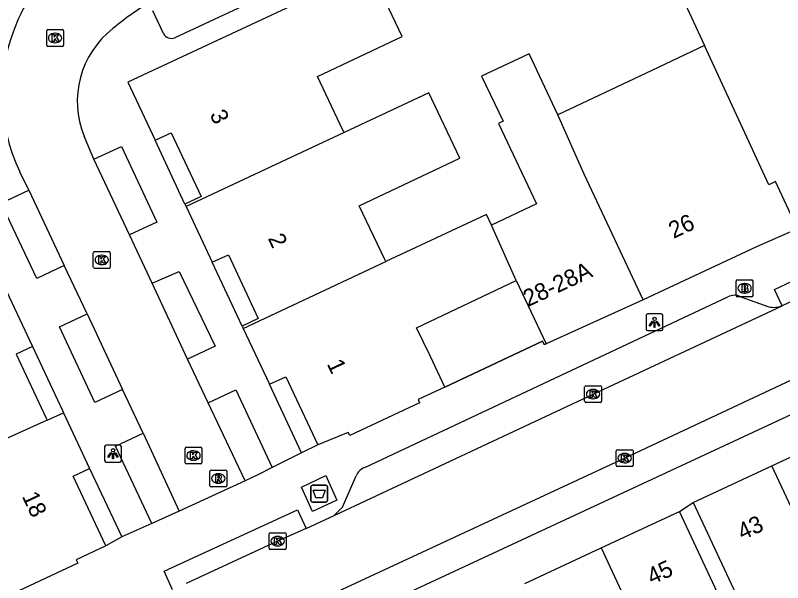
# Model space of a CAD drawing. Extents: x 160379 to 161131, y 383940 to 384849.
# Drawn here: x 160926.47 to 160972.04, y 384296.02 to 384329.72 of the extents above; entities that cross this region are included whole.
import ezdxf

# ---------------------------------------------------------------- set-up
doc = ezdxf.new("R2010")
doc.units = 0
for name, color, linetype in [('IMGEO_Afval_apart_plaats', 7, 'Continuous'), ('IMGEO_Brandkraan', 7, 'Continuous'), ('IMGEO_Kolk', 7, 'Continuous'), ('IMGEO_Lichtpunt', 7, 'Continuous'), ('IMGEO_Muur', 7, 'Continuous'), ('IMGEO_Pand', 7, 'Continuous'), ('IMGEO_Pand_nummerreeks', 7, 'Continuous'), ('IMGEO_Rijbaan_lokaal_open', 7, 'Continuous'), ('IMGEO_Rioolput', 7, 'Continuous'), ('IMGEO_Voetpad_gesloten', 7, 'Continuous'), ('IMGEO_Voetpad_open', 7, 'Continuous')]:
    doc.layers.add(name, color=color, linetype=linetype)

msp = doc.modelspace()

# ---------------------------------------------------------------- linework, layer by layer
at = {"layer": 'IMGEO_Afval_apart_plaats'}
for p, q in [((160944.12, 384301.811), (160944.91, 384301.811)), ((160944.91, 384301.811), (160944.12, 384301.811)), ((160944.02, 384300.911), (160944.02, 384301.711)), ((160944.02, 384301.711), (160944.02, 384300.911)), ((160945.01, 384301.711), (160945.01, 384300.911)), ((160945.01, 384300.911), (160945.01, 384301.711)), ((160944.91, 384300.811), (160944.12, 384300.811)), ((160944.12, 384300.811), (160944.91, 384300.811))]:
    msp.add_line(p, q, dxfattribs=at)
msp.add_lwpolyline([(160944.163, 384301.525), (160944.867, 384301.525), (160944.718, 384301.055), (160944.312, 384301.055), (160944.163, 384301.525)], dxfattribs=at)
for centre, start, end in [((160944.12, 384301.711), 90, 180), ((160944.12, 384301.711), 90, 180), ((160944.91, 384301.711), 0, 90), ((160944.91, 384301.711), 360, 90), ((160944.12, 384300.911), 180, 270), ((160944.12, 384300.911), 180, 270), ((160944.91, 384300.911), 270, 0), ((160944.91, 384300.911), 270, 0)]:
    msp.add_arc(centre, 0.1, start, end, dxfattribs=at)
at = {"layer": 'IMGEO_Brandkraan'}
for p, q in [((160969.274, 384313.082), (160969.274, 384313.934)), ((160969.349, 384314.008), (160970.201, 384314.008)), ((160969.762, 384313.788), (160969.787, 384313.788)), ((160970.275, 384313.934), (160970.275, 384313.082)), ((160969.785, 384313.228), (160969.76, 384313.228)), ((160970.201, 384313.008), (160969.349, 384313.008))]:
    msp.add_line(p, q, dxfattribs=at)
for points in [[(160969.274, 384313.082), (160969.274, 384313.934)], [(160969.349, 384314.008), (160970.201, 384314.008)], [(160969.622, 384313.708), (160969.622, 384313.308), (160969.835, 384313.308)], [(160969.853, 384313.708), (160969.622, 384313.708)], [(160970.275, 384313.934), (160970.275, 384313.082)], [(160969.801, 384313.627), (160969.747, 384313.627), (160969.747, 384313.551)], [(160969.747, 384313.551), (160969.8, 384313.551)], [(160969.809, 384313.475), (160969.747, 384313.475), (160969.747, 384313.394)], [(160969.747, 384313.394), (160969.809, 384313.394)], [(160970.201, 384313.008), (160969.349, 384313.008)]]:
    msp.add_lwpolyline(points, dxfattribs=at)
for centre, radius, start, end in [((160969.351, 384313.932), 0.0765, 91.552, 178.448), ((160969.351, 384313.932), 0.0765, 91.552, 178.448), ((160969.857, 384313.563), 0.145, 59.4692, 91.5367), ((160969.882, 384313.61), 0.0922, 285.5137, 58.1501), ((160970.199, 384313.932), 0.0765, 1.552, 88.448), ((160970.199, 384313.932), 0.0765, 1.552, 88.448), ((160969.802, 384313.589), 0.0379, 267.8285, 90.9355), ((160969.81, 384313.434), 0.0404, 269.8759, 90.5077), ((160969.841, 384313.559), 0.251, 268.6676, 293.5347), ((160969.887, 384313.418), 0.105, 301.3115, 78.989), ((160969.351, 384313.084), 0.0765, 181.552, 268.448), ((160969.351, 384313.084), 0.0765, 181.552, 268.448), ((160970.199, 384313.084), 0.0765, 271.552, 358.448), ((160970.199, 384313.084), 0.0765, 271.552, 358.448)]:
    msp.add_arc(centre, radius, start, end, dxfattribs=at)
for centre, major_axis, ratio, start_param, end_param in [((160969.761, 384313.508), (-0.387, 0.002), 0.722429, 4.712389, 7.853982), ((160969.786, 384313.508), (-0.39, 0.002), 0.717154, 1.570796, 4.712389)]:
    msp.add_ellipse(centre, major_axis=major_axis, ratio=ratio, start_param=start_param, end_param=end_param, dxfattribs=at)
at = {"layer": 'IMGEO_Kolk'}
for p, q in [((160928.335, 384327.948), (160928.335, 384328.8)), ((160928.41, 384328.874), (160929.262, 384328.874)), ((160929.336, 384328.8), (160929.336, 384327.948)), ((160928.823, 384328.654), (160928.848, 384328.654)), ((160929.262, 384327.874), (160928.41, 384327.874)), ((160928.846, 384328.094), (160928.821, 384328.094)), ((160931.105, 384314.767), (160931.105, 384315.619)), ((160931.18, 384315.693), (160932.032, 384315.693)), ((160931.593, 384315.473), (160931.618, 384315.473)), ((160932.106, 384315.619), (160932.106, 384314.767)), ((160932.032, 384314.693), (160931.18, 384314.693)), ((160931.616, 384314.913), (160931.591, 384314.913)), ((160960.355, 384307.723), (160961.207, 384307.723)), ((160960.28, 384306.797), (160960.28, 384307.649)), ((160960.768, 384307.503), (160960.793, 384307.503)), ((160961.281, 384307.649), (160961.281, 384306.797)), ((160960.791, 384306.943), (160960.766, 384306.943)), ((160961.207, 384306.723), (160960.355, 384306.723)), ((160936.629, 384304.073), (160937.481, 384304.073)), ((160936.554, 384303.147), (160936.554, 384303.999)), ((160937.042, 384303.853), (160937.067, 384303.853)), ((160937.555, 384303.999), (160937.555, 384303.147)), ((160962.156, 384302.994), (160962.156, 384303.846)), ((160962.231, 384303.92), (160963.083, 384303.92)), ((160962.644, 384303.7), (160962.669, 384303.7)), ((160963.157, 384303.846), (160963.157, 384302.994)), ((160937.065, 384303.293), (160937.04, 384303.293)), ((160937.481, 384303.073), (160936.629, 384303.073)), ((160963.083, 384302.92), (160962.231, 384302.92)), ((160962.667, 384303.14), (160962.642, 384303.14)), ((160941.547, 384298.063), (160941.547, 384298.915)), ((160941.622, 384298.989), (160942.474, 384298.989)), ((160942.035, 384298.769), (160942.06, 384298.769)), ((160942.548, 384298.915), (160942.548, 384298.063)), ((160942.058, 384298.209), (160942.033, 384298.209)), ((160942.474, 384297.989), (160941.622, 384297.989))]:
    msp.add_line(p, q, dxfattribs=at)
for points in [[(160928.335, 384327.948), (160928.335, 384328.8)], [(160928.41, 384328.874), (160929.262, 384328.874)], [(160929.336, 384328.8), (160929.336, 384327.948)], [(160928.656, 384328.574), (160928.779, 384328.574), (160928.779, 384328.423), (160928.909, 384328.574), (160929.073, 384328.574), (160928.927, 384328.423), (160929.08, 384328.174), (160928.928, 384328.174), (160928.843, 384328.338), (160928.779, 384328.271), (160928.779, 384328.174), (160928.656, 384328.174), (160928.656, 384328.574)], [(160929.262, 384327.874), (160928.41, 384327.874)], [(160931.105, 384314.767), (160931.105, 384315.619)], [(160931.18, 384315.693), (160932.032, 384315.693)], [(160932.106, 384315.619), (160932.106, 384314.767)], [(160931.426, 384315.393), (160931.549, 384315.393), (160931.549, 384315.242), (160931.679, 384315.393), (160931.843, 384315.393), (160931.697, 384315.242), (160931.85, 384314.993), (160931.698, 384314.993), (160931.613, 384315.157), (160931.549, 384315.09), (160931.549, 384314.993), (160931.426, 384314.993), (160931.426, 384315.393)], [(160932.032, 384314.693), (160931.18, 384314.693)], [(160960.355, 384307.723), (160961.207, 384307.723)], [(160960.28, 384306.797), (160960.28, 384307.649)], [(160960.601, 384307.423), (160960.724, 384307.423), (160960.724, 384307.272), (160960.854, 384307.423), (160961.018, 384307.423), (160960.872, 384307.272), (160961.025, 384307.023), (160960.873, 384307.023), (160960.788, 384307.187), (160960.724, 384307.12), (160960.724, 384307.023), (160960.601, 384307.023), (160960.601, 384307.423)], [(160961.281, 384307.649), (160961.281, 384306.797)], [(160961.207, 384306.723), (160960.355, 384306.723)], [(160936.629, 384304.073), (160937.481, 384304.073)], [(160936.554, 384303.147), (160936.554, 384303.999)], [(160936.875, 384303.773), (160936.998, 384303.773), (160936.998, 384303.622), (160937.128, 384303.773), (160937.292, 384303.773), (160937.146, 384303.622), (160937.299, 384303.373), (160937.147, 384303.373), (160937.062, 384303.537), (160936.998, 384303.47), (160936.998, 384303.373), (160936.875, 384303.373), (160936.875, 384303.773)], [(160937.555, 384303.999), (160937.555, 384303.147)], [(160962.156, 384302.994), (160962.156, 384303.846)], [(160962.231, 384303.92), (160963.083, 384303.92)], [(160962.477, 384303.62), (160962.6, 384303.62), (160962.6, 384303.469), (160962.73, 384303.62), (160962.894, 384303.62), (160962.748, 384303.469), (160962.901, 384303.22), (160962.749, 384303.22), (160962.664, 384303.384), (160962.6, 384303.317), (160962.6, 384303.22), (160962.477, 384303.22), (160962.477, 384303.62)], [(160963.157, 384303.846), (160963.157, 384302.994)], [(160937.481, 384303.073), (160936.629, 384303.073)], [(160963.083, 384302.92), (160962.231, 384302.92)], [(160941.547, 384298.063), (160941.547, 384298.915)], [(160941.622, 384298.989), (160942.474, 384298.989)], [(160941.868, 384298.689), (160941.991, 384298.689), (160941.991, 384298.538), (160942.121, 384298.689), (160942.285, 384298.689), (160942.139, 384298.538), (160942.292, 384298.289), (160942.14, 384298.289), (160942.055, 384298.453), (160941.991, 384298.386), (160941.991, 384298.289), (160941.868, 384298.289), (160941.868, 384298.689)], [(160942.548, 384298.915), (160942.548, 384298.063)], [(160942.474, 384297.989), (160941.622, 384297.989)]]:
    msp.add_lwpolyline(points, dxfattribs=at)
for centre, start, end in [((160928.412, 384328.798), 91.552, 178.448), ((160928.412, 384328.798), 91.552, 178.448), ((160929.26, 384328.798), 1.552, 88.448), ((160929.26, 384328.798), 1.552, 88.448), ((160928.412, 384327.95), 181.552, 268.448), ((160928.412, 384327.95), 181.552, 268.448), ((160929.26, 384327.95), 271.552, 358.448), ((160929.26, 384327.95), 271.552, 358.448), ((160931.182, 384315.617), 91.552, 178.448), ((160931.182, 384315.617), 91.552, 178.448), ((160932.03, 384315.617), 1.552, 88.448), ((160932.03, 384315.617), 1.552, 88.448), ((160931.182, 384314.769), 181.552, 268.448), ((160931.182, 384314.769), 181.552, 268.448), ((160932.03, 384314.769), 271.552, 358.448), ((160932.03, 384314.769), 271.552, 358.448), ((160960.357, 384307.647), 91.552, 178.448), ((160960.357, 384307.647), 91.552, 178.448), ((160961.205, 384307.647), 1.552, 88.448), ((160961.205, 384307.647), 1.552, 88.448), ((160960.357, 384306.799), 181.552, 268.448), ((160960.357, 384306.799), 181.552, 268.448), ((160961.205, 384306.799), 271.552, 358.448), ((160961.205, 384306.799), 271.552, 358.448), ((160936.631, 384303.997), 91.552, 178.448), ((160936.631, 384303.997), 91.552, 178.448), ((160937.479, 384303.997), 1.552, 88.448), ((160937.479, 384303.997), 1.552, 88.448), ((160962.233, 384303.844), 91.552, 178.448), ((160962.233, 384303.844), 91.552, 178.448), ((160963.081, 384303.844), 1.552, 88.448), ((160963.081, 384303.844), 1.552, 88.448), ((160936.631, 384303.149), 181.552, 268.448), ((160936.631, 384303.149), 181.552, 268.448), ((160937.479, 384303.149), 271.552, 358.448), ((160937.479, 384303.149), 271.552, 358.448), ((160962.233, 384302.996), 181.552, 268.448), ((160962.233, 384302.996), 181.552, 268.448), ((160963.081, 384302.996), 271.552, 358.448), ((160963.081, 384302.996), 271.552, 358.448), ((160941.624, 384298.913), 91.552, 178.448), ((160941.624, 384298.913), 91.552, 178.448), ((160942.472, 384298.913), 1.552, 88.448), ((160942.472, 384298.913), 1.552, 88.448), ((160941.624, 384298.065), 181.552, 268.448), ((160941.624, 384298.065), 181.552, 268.448), ((160942.472, 384298.065), 271.552, 358.448), ((160942.472, 384298.065), 271.552, 358.448)]:
    msp.add_arc(centre, 0.0765, start, end, dxfattribs=at)
for centre, major_axis, ratio, start_param, end_param in [((160928.822, 384328.374), (-0.387, 0.002), 0.722429, 4.712389, 7.853982), ((160928.847, 384328.374), (-0.39, 0.002), 0.717154, 1.570796, 4.712389), ((160931.592, 384315.193), (-0.387, 0.002), 0.722429, 4.712389, 7.853982), ((160931.617, 384315.193), (-0.39, 0.002), 0.717154, 1.570796, 4.712389), ((160960.767, 384307.223), (-0.387, 0.002), 0.722429, 4.712389, 7.853982), ((160960.792, 384307.223), (-0.39, 0.002), 0.717154, 1.570796, 4.712389), ((160937.041, 384303.573), (-0.387, 0.002), 0.722429, 4.712389, 7.853982), ((160937.066, 384303.573), (-0.39, 0.002), 0.717154, 1.570796, 4.712389), ((160962.643, 384303.42), (-0.387, 0.002), 0.722429, 4.712389, 7.853982), ((160962.668, 384303.42), (-0.39, 0.002), 0.717154, 1.570796, 4.712389), ((160942.034, 384298.489), (-0.387, 0.002), 0.722429, 4.712389, 7.853982), ((160942.059, 384298.489), (-0.39, 0.002), 0.717154, 1.570796, 4.712389)]:
    msp.add_ellipse(centre, major_axis=major_axis, ratio=ratio, start_param=start_param, end_param=end_param, dxfattribs=at)
at = {"layer": 'IMGEO_Lichtpunt'}
for p, q in [((160963.93, 384311.894), (160963.93, 384311.087)), ((160963.93, 384311.894), (160963.93, 384311.087)), ((160964.832, 384311.989), (160964.024, 384311.989)), ((160964.832, 384311.989), (160964.024, 384311.989)), ((160964.926, 384311.087), (160964.926, 384311.894)), ((160964.926, 384311.087), (160964.926, 384311.894)), ((160964.024, 384310.993), (160964.832, 384310.993)), ((160964.024, 384310.993), (160964.832, 384310.993)), ((160931.775, 384304.089), (160931.775, 384303.282)), ((160931.775, 384304.089), (160931.775, 384303.282)), ((160932.677, 384304.184), (160931.869, 384304.184)), ((160932.677, 384304.184), (160931.869, 384304.184)), ((160932.771, 384303.282), (160932.771, 384304.089)), ((160932.771, 384303.282), (160932.771, 384304.089)), ((160931.869, 384303.188), (160932.677, 384303.188)), ((160931.869, 384303.188), (160932.677, 384303.188))]:
    msp.add_line(p, q, dxfattribs=at)
for points in [[(160964.304, 384311.558), (160964.343, 384311.53), (160964.155, 384311.268), (160964.117, 384311.295), (160964.304, 384311.558)], [(160964.406, 384311.51), (160964.453, 384311.51), (160964.453, 384311.188), (160964.406, 384311.188), (160964.406, 384311.51)], [(160964.516, 384311.53), (160964.554, 384311.557), (160964.741, 384311.295), (160964.702, 384311.267), (160964.516, 384311.53)], [(160932.149, 384303.753), (160932.188, 384303.725), (160932, 384303.463), (160931.962, 384303.49), (160932.149, 384303.753)], [(160932.251, 384303.705), (160932.298, 384303.705), (160932.298, 384303.383), (160932.251, 384303.383), (160932.251, 384303.705)], [(160932.361, 384303.725), (160932.399, 384303.752), (160932.586, 384303.49), (160932.547, 384303.462), (160932.361, 384303.725)]]:
    msp.add_lwpolyline(points, dxfattribs=at)
for centre in [(160964.429, 384311.692), (160932.274, 384303.887)]:
    msp.add_circle(centre, 0.0994, dxfattribs=at)
for centre, start, end in [((160964.024, 384311.894), 90, 180), ((160964.024, 384311.894), 90, 180), ((160964.832, 384311.894), 0, 90), ((160964.832, 384311.894), 0, 90), ((160964.024, 384311.087), 180, 270), ((160964.024, 384311.087), 180, 270), ((160964.832, 384311.087), 270, 0), ((160964.832, 384311.087), 270, 360), ((160931.869, 384304.089), 90, 180), ((160931.869, 384304.089), 90, 180), ((160932.677, 384304.089), 0, 90), ((160932.677, 384304.089), 0, 90), ((160931.869, 384303.282), 180, 270), ((160931.869, 384303.282), 180, 270), ((160932.677, 384303.282), 270, 0), ((160932.677, 384303.282), 270, 360)]:
    msp.add_arc(centre, 0.0946, start, end, dxfattribs=at)
at = {"layer": 'IMGEO_Muur'}
msp.add_lwpolyline([(160951.971, 384307.639), (160957.784, 384310.362), (160957.882, 384310.168), (160957.991, 384310.215)], dxfattribs=at)
at = {"layer": 'IMGEO_Pand'}
for points in [[(160986.764, 384323.863), (160984.723, 384328.376), (160978.345, 384325.492), (160970.86, 384342.047), (160970.802, 384342.176), (160962.547, 384338.444), (160963.028, 384337.381), (160967.394, 384327.922)], [(160947.54, 384332.492), (160933.153, 384325.75), (160934.769, 384322.306)], [(160945.998, 384322.759), (160945.93, 384322.902), (160944.422, 384326.089), (160949.445, 384328.465), (160947.872, 384331.78)], [(160967.394, 384327.922), (160964.262, 384326.443), (160958.689, 384323.812)], [(160972.915, 384317.036), (160971.617, 384319.849), (160971.207, 384319.66), (160967.394, 384327.922)], [(160958.689, 384323.812), (160956.981, 384327.431), (160954.164, 384326.101), (160955.439, 384323.444), (160955.167, 384323.299), (160957.421, 384318.523), (160954.745, 384317.261)], [(160948.469, 384315.09), (160948.406, 384315.223), (160946.898, 384318.41), (160952.866, 384321.233), (160951.029, 384325.118), (160945.998, 384322.759)], [(160963.756, 384312.813), (160960.245, 384320.279), (160958.689, 384323.812)], [(160945.998, 384322.759), (160936.616, 384318.359)], [(160934.769, 384322.306), (160935.729, 384322.738), (160937.505, 384318.958), (160936.546, 384318.507)], [(160936.546, 384318.507), (160936.616, 384318.359)], [(160936.616, 384318.359), (160938.168, 384315.064)], [(160954.745, 384317.261), (160954.446, 384317.893), (160948.469, 384315.09)], [(160956.22, 384313.969), (160954.745, 384317.261)], [(160972.915, 384317.036), (160970.492, 384315.969), (160963.756, 384312.813)], [(160938.168, 384315.064), (160939.126, 384315.49), (160940.896, 384311.715), (160939.938, 384311.263)], [(160940.005, 384311.12), (160948.469, 384315.09)], [(160951.971, 384307.639), (160951.124, 384309.451), (160950.301, 384311.169), (160956.22, 384313.969)], [(160956.22, 384313.969), (160957.991, 384310.215)], [(160925.942, 384313.332), (160927.484, 384310.051)], [(160963.756, 384312.813), (160957.991, 384310.215)], [(160939.938, 384311.263), (160940.005, 384311.12)], [(160940.005, 384311.12), (160941.562, 384307.822)], [(160927.484, 384310.051), (160926.515, 384309.596), (160928.296, 384305.801), (160928.359, 384305.666)], [(160941.562, 384307.822), (160942.534, 384308.258), (160944.43, 384304.212)], [(160951.971, 384307.639), (160950.387, 384306.899), (160950.48, 384306.7), (160946.332, 384304.758), (160946.228, 384304.951), (160944.43, 384304.212)], [(160928.359, 384305.666), (160929.335, 384306.106)], [(160929.335, 384306.106), (160930.883, 384302.804)], [(160928.359, 384305.666), (160920.833, 384302.277)], [(160971.397, 384302.97), (160975.936, 384305.09)], [(160931.856, 384298.207), (160929.914, 384302.349), (160930.883, 384302.804)], [(160966.725, 384300.787), (160971.397, 384302.97)], [(160976.778, 384291.455), (160971.397, 384302.97)], [(160966.725, 384300.787), (160968.838, 384296.256), (160969.791, 384294.212), (160972.128, 384295.302), (160974.433, 384290.361), (160975.474, 384288.13), (160977.82, 384289.225), (160976.778, 384291.455)], [(160961.251, 384298.083), (160965.905, 384300.254)], [(160967.227, 384285.275), (160969.904, 384286.524), (160969.275, 384287.873), (160966.956, 384292.844), (160969.172, 384293.879), (160968.932, 384294.393), (160968.693, 384294.281), (160968.02, 384295.724), (160965.905, 384300.254)], [(160931.856, 384298.207), (160930.084, 384297.372), (160930.176, 384297.181), (160926.009, 384295.223), (160925.916, 384295.423), (160924.353, 384294.682)], [(160956.733, 384295.975), (160961.251, 384298.083)], [(160961.251, 384298.083), (160967.227, 384285.275)]]:
    msp.add_lwpolyline(points, dxfattribs=at)
at = {"layer": 'IMGEO_Rijbaan_lokaal_open'}
for points in [[(161021.201, 384330.613), (161016.858, 384328.577), (161000, 384320.783), (160999.805, 384320.693), (160982.125, 384312.545), (160962.657, 384303.421), (160944.731, 384295.078), (160938.42, 384292.1)], [(160931.139, 384321.177), (160930.557, 384322.54)], [(160933.251, 384316.674), (160931.139, 384321.177)], [(160927.271, 384319.339), (160926.749, 384320.427)], [(160927.271, 384319.339), (160929.382, 384314.856)], [(160934.591, 384313.808), (160933.251, 384316.674)], [(160930.732, 384311.991), (160929.382, 384314.856)], [(160975.614, 384314.162), (160971.999, 384312.472)], [(160936.702, 384309.292), (160934.591, 384313.808)], [(160945.401, 384300.015), (160960.781, 384307.221), (160971.999, 384312.472)], [(160930.732, 384311.991), (160932.832, 384307.498)], [(160937.916, 384306.695), (160936.702, 384309.292)], [(160934.058, 384304.909), (160932.832, 384307.498)], [(160940.112, 384302.066), (160937.916, 384306.695)], [(160934.058, 384304.909), (160936.211, 384300.27)], [(160940.112, 384302.066), (160936.211, 384300.27)], [(160943.738, 384299.236), (160945.401, 384300.015)], [(160943.738, 384299.236), (160942.048, 384298.488), (160936.625, 384295.974)]]:
    msp.add_lwpolyline(points, dxfattribs=at)
for centre, radius, start, end in [((160934.911, 384325.947), 8.989, 121.9944, 156.7637), ((160943.156, 384316.018), 16.889, 119.6957, 130.1356), ((160936.268, 384325.062), 10.588, 155.2624, 205.9636), ((160935.613, 384324.61), 5.463, 127.7412, 202.2621)]:
    msp.add_arc(centre, radius, start, end, dxfattribs=at)
at = {"layer": 'IMGEO_Rioolput'}
for p, q in [((160938.103, 384302.71), (160938.955, 384302.71)), ((160938.028, 384301.784), (160938.028, 384302.636)), ((160938.516, 384302.49), (160938.541, 384302.49)), ((160939.029, 384302.636), (160939.029, 384301.784)), ((160938.539, 384301.93), (160938.514, 384301.93)), ((160938.955, 384301.71), (160938.103, 384301.71))]:
    msp.add_line(p, q, dxfattribs=at)
for points in [[(160938.103, 384302.71), (160938.955, 384302.71)], [(160938.028, 384301.784), (160938.028, 384302.636)], [(160938.617, 384302.408), (160938.365, 384302.41), (160938.365, 384302.01)], [(160938.543, 384302.329), (160938.489, 384302.329), (160938.489, 384302.248)], [(160938.489, 384302.248), (160938.541, 384302.248)], [(160939.029, 384302.636), (160939.029, 384301.784)], [(160938.365, 384302.01), (160938.489, 384302.01), (160938.489, 384302.172), (160938.5, 384302.172)], [(160938.547, 384302.143), (160938.618, 384302.01), (160938.758, 384302.01), (160938.693, 384302.136)], [(160938.955, 384301.71), (160938.103, 384301.71)]]:
    msp.add_lwpolyline(points, dxfattribs=at)
for centre, radius, start, end in [((160938.105, 384302.634), 0.0765, 91.552, 178.448), ((160938.105, 384302.634), 0.0765, 91.552, 178.448), ((160938.953, 384302.634), 0.0765, 1.552, 88.448), ((160938.953, 384302.634), 0.0765, 1.552, 88.448), ((160938.525, 384302.437), 0.19, 274.7715, 282.9687), ((160938.549, 384302.233), 0.0964, 77.0061, 93.1865), ((160938.563, 384302.29), 0.0378, 276.6634, 79.6772), ((160938.616, 384302.298), 0.109, 350.3612, 89.416), ((160938.614, 384302.298), 0.112, 277.5842, 350.9817), ((160938.499, 384302.119), 0.0533, 26.0293, 88.6989), ((160938.598, 384302.083), 0.108, 29.5134, 73.7905), ((160938.105, 384301.786), 0.0765, 181.552, 268.448), ((160938.105, 384301.786), 0.0765, 181.552, 268.448), ((160938.953, 384301.786), 0.0765, 271.552, 358.448), ((160938.953, 384301.786), 0.0765, 271.552, 358.448)]:
    msp.add_arc(centre, radius, start, end, dxfattribs=at)
for centre, major_axis, ratio, start_param, end_param in [((160938.515, 384302.21), (-0.387, 0.002), 0.722429, 4.712389, 7.853982), ((160938.54, 384302.21), (-0.39, 0.002), 0.717154, 1.570796, 4.712389)]:
    msp.add_ellipse(centre, major_axis=major_axis, ratio=ratio, start_param=start_param, end_param=end_param, dxfattribs=at)
at = {"layer": 'IMGEO_Voetpad_gesloten'}
msp.add_lwpolyline([(160945.563, 384300.919), (160944.114, 384300.24), (160943.466, 384301.703), (160944.915, 384302.382), (160945.563, 384300.919)], dxfattribs=at)
at = {"layer": 'IMGEO_Voetpad_open'}
for points in [[(160945.548, 384332.885), (160935.936, 384328.385)], [(160935.275, 384328.634), (160934.63, 384329.983)], [(161019.512, 384327.87), (161000, 384318.788), (160934.837, 384288.458), (160894.523, 384269.636)], [(160936.546, 384318.507), (160934.769, 384322.306)], [(160931.139, 384321.177), (160932.78, 384321.928), (160934.883, 384317.441), (160933.251, 384316.674)], [(160929.382, 384314.856), (160927.759, 384314.094), (160925.641, 384318.57), (160927.271, 384319.339)], [(160939.938, 384311.263), (160938.168, 384315.064)], [(160971.999, 384312.472), (160971.546, 384313.442), (160975.161, 384315.132), (160975.614, 384314.162)], [(160934.591, 384313.808), (160936.195, 384314.502), (160938.341, 384310.067), (160936.702, 384309.292)], [(160947.259, 384302.875), (160968.782, 384312.995)], [(160969.557, 384313.007), (160971.225, 384312.408)], [(160932.832, 384307.498), (160931.204, 384306.734), (160929.095, 384311.21), (160930.732, 384311.991)], [(160927.484, 384310.051), (160929.265, 384306.255), (160929.335, 384306.106)], [(160957.991, 384310.215), (160957.882, 384310.168), (160957.784, 384310.362), (160951.971, 384307.639)], [(160943.465, 384303.728), (160941.562, 384307.822)], [(160937.916, 384306.695), (160939.559, 384307.476), (160941.725, 384302.856)], [(160934.579, 384299.543), (160932.422, 384304.139), (160934.058, 384304.909)], [(160944.43, 384304.212), (160943.465, 384303.728)], [(160943.465, 384303.728), (160941.725, 384302.856)], [(160930.883, 384302.804), (160932.791, 384298.746)], [(160941.725, 384302.856), (160940.874, 384302.43), (160940.112, 384302.066)], [(160945.401, 384300.015), (160945.91, 384300.504), (160946.707, 384302.362)], [(160965.905, 384300.254), (160966.725, 384300.787)], [(160936.211, 384300.27), (160934.579, 384299.543)], [(160935.814, 384295.602), (160935.306, 384296.711), (160943.233, 384300.347), (160943.738, 384299.236)], [(160934.579, 384299.543), (160932.791, 384298.746)], [(160932.791, 384298.746), (160931.856, 384298.207)]]:
    msp.add_lwpolyline(points, dxfattribs=at)
for centre, radius, start, end in [((160935.744, 384328.878), 0.529, 207.4847, 291.2323), ((160969.182, 384312.212), 0.879, 64.7355, 117.0387), ((160971.511, 384313.658), 1.282, 257.1002, 292.3536), ((160947.526, 384302.034), 0.882, 107.6125, 158.193)]:
    msp.add_arc(centre, radius, start, end, dxfattribs=at)

# ---------------------------------------------------------------- texts
at = {"layer": 'IMGEO_Pand_nummerreeks'}
for s, rotation, p in [('3', 295.1584, (160937.996, 384323.838)), ('26', 25.1032, (160965.559, 384316.441)), ('2', 295.1584, (160941.451, 384316.483)), ('28-28A', 25.1018, (160956.921, 384312.393)), ('1', 295.1584, (160944.956, 384309.021)), ('18', 295.1354, (160926.85, 384301.155)), ('43', 25.044, (160969.645, 384298.529)), ('45', 25.012, (160964.275, 384295.875))]:
    msp.add_text(s, height=1, rotation=rotation, dxfattribs=at).set_placement(p)

doc.saveas('drawing.dxf')
